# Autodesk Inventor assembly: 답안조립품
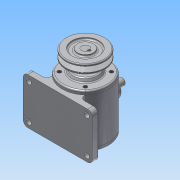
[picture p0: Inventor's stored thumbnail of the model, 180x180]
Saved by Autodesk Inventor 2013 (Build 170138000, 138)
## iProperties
Created: 2015-08
Part Number: 답안조립품
Document SubType Name: Assembly
Designer: Administrator
Author: Administrator
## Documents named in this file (14)
- C:\Users\Administrator\Desktop\350806V1036\답안조립품.iam
- C:\Users\Administrator\Desktop\350806V1036\본체.ipt
- C:\Users\Administrator\Desktop\350806V1036\KS B 1028  - 납작점M4x5.ipt
- C:\Users\Administrator\Desktop\350806V1036\KS B 1311 - 5 x 5 x 18I.ipt
- C:\Users\Administrator\Desktop\350806V1036\M4-소켓머리.ipt
- C:\Users\Administrator\Desktop\350806V1036\V-벨트풀리.ipt
- C:\Users\Administrator\Desktop\350806V1036\뒷커버.ipt
- C:\Users\Administrator\Desktop\350806V1036\베어링 6203.ipt
- C:\Users\Administrator\Desktop\350806V1036\부시.ipt
- C:\Users\Administrator\Desktop\350806V1036\스프링.ipt
- C:\Users\Administrator\Desktop\350806V1036\슬라이더.ipt
- C:\Users\Administrator\Desktop\350806V1036\앞커버.ipt
- C:\Users\Administrator\Desktop\350806V1036\오일실.ipt
- C:\Users\Administrator\Desktop\350806V1036\축.ipt
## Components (14 placed, 6 different names)
1. KS B 1028 납작점 - 미터 납작점M4x5:1
2. KS B 1311 (I) 5 x 5 x 18:1
3. V-벨트풀리:1 — 플러쉬:1
4. 8-오일실:1
5. 7-베어링 6203:1
6. 7-베어링 6203:2
7. 9-M4-소켓머리:1
8. 9-M4-소켓머리:3
9. 9-M4-소켓머리:4
10. 9-M4-소켓머리:5
11. 9-M4-소켓머리:2
12. 9-M4-소켓머리:6
13. 9-M4-소켓머리:7
14. 9-M4-소켓머리:8
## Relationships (1: Flush 1)
- 플러쉬:1 [Flush]: V-벨트풀리:1
